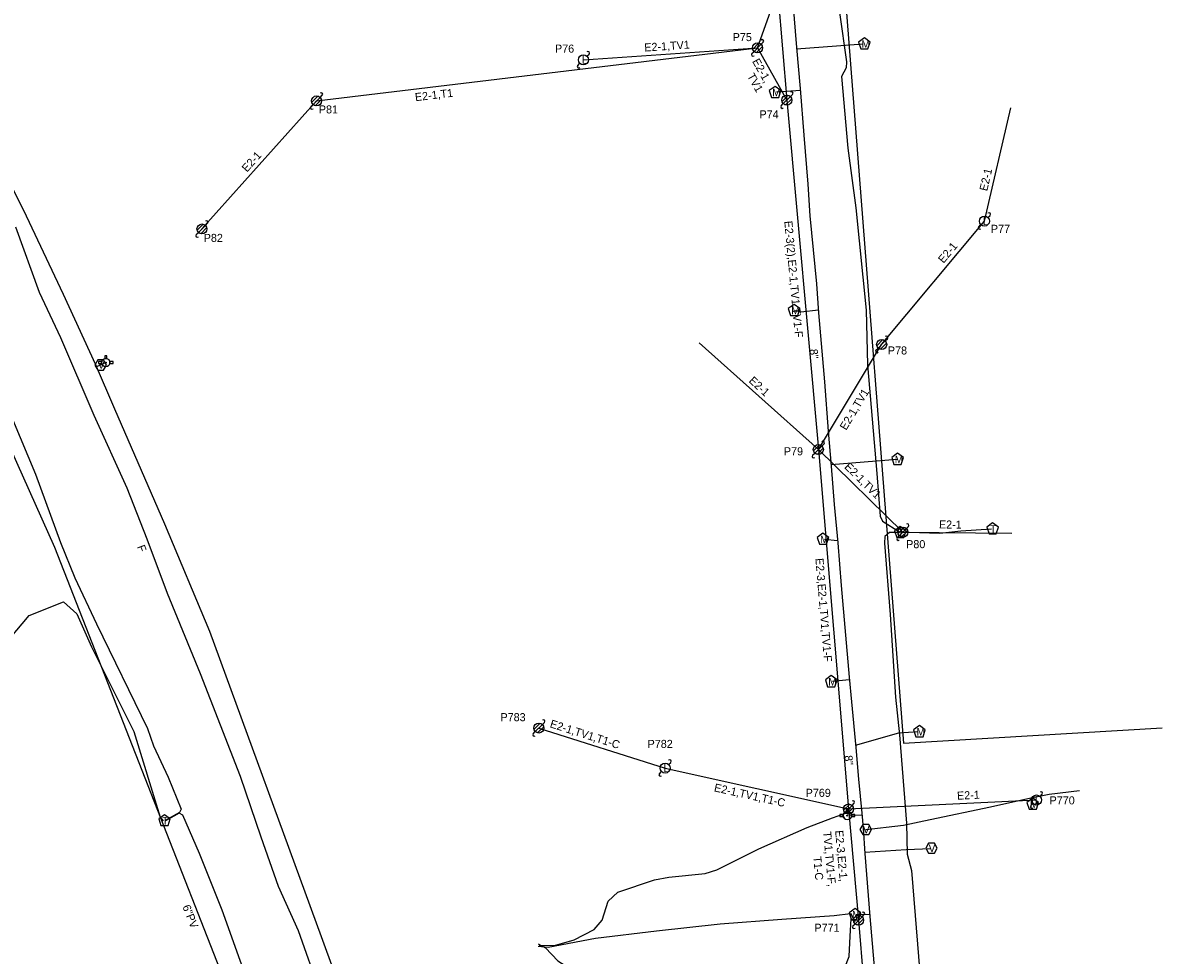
# Model space of a CAD drawing. Extents: x 1741604 to 1825760, y 1164229 to 1194908.
# Drawn here: x 1755902 to 1756469, y 1167980 to 1168443 of the extents above; entities that cross this region are included whole.
import ezdxf

# ---------------------------------------------------------------- set-up
doc = ezdxf.new("R2010")
doc.units = 0
for name, color, linetype in [('RD_EX_SU_Elec', 7, 'Continuous'), ('RD_EX_SU_H2O', 7, 'Continuous'), ('RD_EX_SU_Ovhd', 7, 'Continuous'), ('RD_EX_SU_Pole', 7, 'Continuous'), ('RD_EX_SU_Sewer', 7, 'Continuous'), ('RD_EX_SU_Telecom', 7, 'Continuous'), ('RD_EX_SU_TX_H2O', 7, 'Continuous'), ('RD_EX_SU_TX_Pole', 7, 'Continuous'), ('RD_EX_SU_TX_Sewer', 7, 'Continuous'), ('RD_EX_SU_TX_Telecom', 7, 'Continuous')]:
    doc.layers.add(name, color=color, linetype=linetype)

# ---------------------------------------------------------------- blocks, each defined once
blk = doc.blocks.new('SUE_PP')
at = {"layer": 'RD_EX_SU_Pole'}
for p, q in [((-2.41, -0.65), (0.65, 2.41)), ((-1.77, -1.77), (1.77, 1.77)), ((-0.65, -2.41), (2.41, 0.65)), ((1.77, 1.77), (2.83, 2.83)), ((-2.83, -2.83), (-1.77, -1.77))]:
    blk.add_line(p, q, dxfattribs=at)
blk.add_circle((0, 0), 2.5, dxfattribs=at)
for centre, start, end in [((2.3, 3.36), 315, 135), ((-2.3, -3.36), 135, 315)]:
    blk.add_arc(centre, 0.75, start, end, dxfattribs=at)
blk = doc.blocks.new('SUE_WM')
at = {"layer": 'RD_EX_SU_H2O'}
blk.add_lwpolyline([(0, 3.05), (-2.9, 0.94), (-1.79, -2.47), (1.79, -2.47), (2.9, 0.94)], close=True, dxfattribs=at)
blk.add_text('M', height=3.75, dxfattribs=at).set_placement((-1.43, -1.88))
blk = doc.blocks.new('SUE_TPP')
at = {"layer": 'RD_EX_SU_Telecom'}
blk.add_lwpolyline([(0, 3), (-2.85, 0.93), (-1.76, -2.43), (1.76, -2.43), (2.85, 0.93)], close=True, dxfattribs=at)
blk.add_text('T', height=3.75, dxfattribs=at).set_placement((-1.25, -1.88))
blk = doc.blocks.new('SUE_WFH')
at = {"layer": 'RD_EX_SU_H2O'}
for p, q in [((-2.01, 0.6), (-3.65, 0.6)), ((-3.65, 0.6), (-3.65, -0.45)), ((-0.48, 3.38), (-0.48, 2.04)), ((0.57, 3.38), (-0.48, 3.38)), ((0.57, 2.02), (0.57, 3.38)), ((3.7, 0.6), (2.01, 0.6)), ((3.7, -0.45), (3.7, 0.6)), ((-3.65, -0.45), (-2.05, -0.45)), ((2.05, -0.45), (3.7, -0.45))]:
    blk.add_line(p, q, dxfattribs=at)
for radius in [2.1, 0.263]:
    blk.add_circle((0, 0), radius, dxfattribs=at)
for start, end in [(163.3387, 192.315), (74.2455, 103.2128), (347.685, 16.6613)]:
    blk.add_arc((0, 0), 2.1, start, end, dxfattribs=at)
blk = doc.blocks.new('SUE_WV')
at = {"layer": 'RD_EX_SU_H2O'}
blk.add_lwpolyline([(2.89, 0), (1.44, 2.5), (-1.44, 2.5), (-2.89, 0), (-1.44, -2.5), (1.44, -2.5)], close=True, dxfattribs=at)
blk.add_text('V', height=3.75, dxfattribs=at).set_placement((-1.43, -1.88))

msp = doc.modelspace()

# ---------------------------------------------------------------- linework, layer by layer
at = {"layer": 'RD_EX_SU_Elec'}
msp.add_lwpolyline([(1756158.7, 1167983.99), (1756163.59, 1167983.56), (1756187.17, 1167988.03), (1756217.4, 1167991.66), (1756249.02, 1167995.12), (1756279.77, 1167997.42), (1756305.79, 1167999.38), (1756313.88, 1168000.27), (1756316.19, 1167996.26)], dxfattribs=at)
at = {"layer": 'RD_EX_SU_H2O'}
for p, q in [((1756287.04, 1168430.3), (1756320.14, 1168432.8)), ((1756288.92, 1168409.56), (1756276.99, 1168408.7)), ((1755943.15, 1168273.87), (1755939.17, 1168272.13)), ((1756304.2, 1168223.57), (1756336.98, 1168226.24)), ((1756307.47, 1168185.66), (1756300.96, 1168186.31)), ((1756313.25, 1168116.46), (1756304.98, 1168115.68)), ((1756404.41, 1168055.03), (1756404.06, 1168057.9)), ((1756319.41, 1168049.21), (1756313.16, 1168048.96)), ((1756323.32, 1167999.75), (1756316.73, 1167999.65))]:
    msp.add_line(p, q, dxfattribs=at)
for points in [[(1755726.87, 1168521.3), (1755747.63, 1168505.06), (1755777.82, 1168480.62), (1755829.49, 1168441.52), (1755856.27, 1168421.17), (1755874.43, 1168407.88), (1755891.14, 1168373.18), (1755904.2, 1168347.14)], [(1756285.17, 1168453.36), (1756286.98, 1168430.89), (1756288.84, 1168410.54), (1756290.69, 1168387.38), (1756292.59, 1168362.89), (1756293.61, 1168347.16), (1756296.92, 1168313.47), (1756298.02, 1168299), (1756300.93, 1168264.73), (1756302.72, 1168240.2), (1756304.28, 1168222.7), (1756305.65, 1168203.75), (1756307.59, 1168184.55), (1756309.19, 1168163.34), (1756313.11, 1168117.87), (1756314.27, 1168105.58), (1756316.49, 1168082.9), (1756317.85, 1168067.08)], [(1755904.2, 1168347.14), (1755922.61, 1168308.3), (1755938.52, 1168273.68), (1755948, 1168251.19), (1755972.99, 1168194.09), (1755995.27, 1168140.77), (1756050.84, 1167988.86), (1756081.08, 1167905.61)], [(1756297.93, 1168300.23), (1756289.24, 1168299.38), (1756286.37, 1168299.96)], [(1756316.37, 1168084.09), (1756337.79, 1168090.19), (1756347.49, 1168090.77)], [(1756317.85, 1168067.08), (1756319.54, 1168050.19), (1756320.11, 1168042.67), (1756320.97, 1168030.07), (1756323.39, 1167998.84), (1756327.05, 1167956.56), (1756331.25, 1167904.83), (1756337.4, 1167830.13), (1756339.37, 1167804.89), (1756341.64, 1167782.73), (1756346.05, 1167725.54), (1756348.16, 1167704.76), (1756350.69, 1167674.25), (1756356.07, 1167614.92), (1756363.99, 1167527.76)], [(1756320.16, 1168041.86), (1756340.19, 1168044.22), (1756353.43, 1168047.04), (1756383.46, 1168053.37), (1756403.52, 1168057.78), (1756412.53, 1168059.65), (1756427.58, 1168061.53)], [(1756320.92, 1168030.83), (1756341.5, 1168032.11), (1756353.7, 1168032.64)]]:
    msp.add_lwpolyline(points, dxfattribs=at)
at = {"layer": 'RD_EX_SU_Ovhd'}
for p, q in [((1756267.62, 1168578.94), (1756282.23, 1168404.77)), ((1756267.68, 1168430.74), (1756309.52, 1168548.91)), ((1756048.5, 1168404.33), (1756267.68, 1168430.74)), ((1756181.09, 1168424.8), (1756267.68, 1168430.74)), ((1756267.68, 1168430.74), (1756282.23, 1168404.77)), ((1756282.23, 1168404.77), (1756297.87, 1168230.98)), ((1755991.54, 1168340.68), (1756048.5, 1168404.33)), ((1756380.41, 1168344.61), (1756393.49, 1168400.89)), ((1756329.33, 1168283.25), (1756380.41, 1168344.61)), ((1756238.72, 1168284), (1756297.87, 1168230.98)), ((1756297.87, 1168230.98), (1756329.33, 1168283.25)), ((1756297.87, 1168230.98), (1756339.88, 1168189.94)), ((1756297.87, 1168230.98), (1756312.84, 1168052.28)), ((1756339.88, 1168189.94), (1756394.05, 1168189.45)), ((1756158.95, 1168092.53), (1756221.7, 1168072.64)), ((1756221.7, 1168072.64), (1756312.84, 1168052.28)), ((1756312.84, 1168052.28), (1756406.3, 1168056.76)), ((1756312.84, 1168052.28), (1756317.86, 1167996.94)), ((1756317.86, 1167996.94), (1756327.05, 1167883.97))]:
    msp.add_line(p, q, dxfattribs=at)
at = {"layer": 'RD_EX_SU_Pole'}
for p, q in [((1756182.85, 1168426.57), (1756183.92, 1168427.63)), ((1756178.26, 1168421.98), (1756179.32, 1168423.04)), ((1756046.08, 1168403.69), (1756049.15, 1168406.75)), ((1756046.73, 1168402.57), (1756050.27, 1168406.1)), ((1756047.85, 1168401.92), (1756050.91, 1168404.98)), ((1756050.27, 1168406.1), (1756051.33, 1168407.16)), ((1756045.67, 1168401.51), (1756046.73, 1168402.57)), ((1755989.13, 1168340.03), (1755992.19, 1168343.1)), ((1755989.78, 1168338.91), (1755993.31, 1168342.45)), ((1755993.31, 1168342.45), (1755994.37, 1168343.51)), ((1756377.58, 1168341.79), (1756378.65, 1168342.85)), ((1756382.18, 1168346.38), (1756383.24, 1168347.44)), ((1755988.72, 1168337.85), (1755989.78, 1168338.91)), ((1755990.9, 1168338.27), (1755993.96, 1168341.33)), ((1756337.46, 1168189.29), (1756340.52, 1168192.35)), ((1756338.11, 1168188.17), (1756341.64, 1168191.71)), ((1756339.23, 1168187.53), (1756342.29, 1168190.59)), ((1756341.64, 1168191.71), (1756342.7, 1168192.77)), ((1756337.05, 1168187.11), (1756338.11, 1168188.17)), ((1756218.87, 1168069.81), (1756219.93, 1168070.87)), ((1756223.47, 1168074.41), (1756224.53, 1168075.47)), ((1756408.06, 1168058.53), (1756409.12, 1168059.59)), ((1756403.47, 1168053.93), (1756404.53, 1168054.99))]:
    msp.add_line(p, q, dxfattribs=at)
for centre in [(1756181.09, 1168424.8), (1756048.5, 1168404.33), (1755991.54, 1168340.68), (1756380.41, 1168344.61), (1756339.88, 1168189.94), (1756221.7, 1168072.64), (1756406.3, 1168056.76)]:
    msp.add_circle(centre, 2.5, dxfattribs=at)
for centre, start, end in [((1756183.39, 1168428.16), 315, 135), ((1756178.79, 1168421.45), 135, 315), ((1756050.8, 1168407.69), 315, 135), ((1756046.2, 1168400.98), 135, 315), ((1756382.71, 1168347.97), 315, 135), ((1755993.84, 1168344.04), 315, 135), ((1755989.25, 1168337.32), 135, 315), ((1756378.11, 1168341.26), 135, 315), ((1756342.17, 1168193.3), 315, 135), ((1756337.58, 1168186.58), 135, 315), ((1756224, 1168076), 315, 135), ((1756219.4, 1168069.28), 135, 315), ((1756408.59, 1168060.12), 315, 135), ((1756404, 1168053.4), 135, 315)]:
    msp.add_arc(centre, 0.75, start, end, dxfattribs=at)
at = {"layer": 'RD_EX_SU_Sewer'}
for points in [[(1756311.13, 1168456.78), (1756340.11, 1168085.05), (1756468.76, 1168092.7)], [(1755893.01, 1168238.82), (1755918.27, 1168182.4)], [(1755918.27, 1168182.4), (1756052.9, 1167838.38)]]:
    msp.add_lwpolyline(points, dxfattribs=at)
at = {"layer": 'RD_EX_SU_Telecom'}
for points in [[(1756308.42, 1168448.32), (1756311.91, 1168423.81), (1756311.76, 1168420.79), (1756309.33, 1168416.48), (1756312.58, 1168380.89), (1756316.49, 1168351.19), (1756321.57, 1168300.36), (1756322.32, 1168273.16), (1756326.95, 1168219.13), (1756328.55, 1168197.8), (1756329.78, 1168195.34), (1756338.22, 1168190.16)], [(1755898.9, 1168341.72), (1755910.59, 1168309.21), (1755921.23, 1168286.67), (1755937.77, 1168248.04), (1755954.25, 1168211.92), (1755964.15, 1168186.62), (1755974.26, 1168159.56), (1755990.65, 1168119.67), (1756010.52, 1168068.56), (1756020.83, 1168038.51), (1756029.44, 1168013.84), (1756039.32, 1167991.87), (1756050.05, 1167961.32)], [(1755867.59, 1168310.21), (1755881.89, 1168280.5), (1755897.42, 1168246.03), (1755908.8, 1168218.82), (1755921.3, 1168184.71), (1755928.36, 1168167.28), (1755939.17, 1168144.41), (1755964.51, 1168092.26), (1755967.52, 1168083.62), (1755974.77, 1168068.14), (1755981.19, 1168052.22), (1755980.43, 1168050.52), (1755973.2, 1168046.59)], [(1756338.16, 1168189.78), (1756333.21, 1168189.81), (1756330.86, 1168187.79), (1756330.68, 1168184.52), (1756333.54, 1168148.9), (1756336.25, 1168107.92), (1756338.14, 1168089.1), (1756341.61, 1168045.19), (1756342.02, 1168029.89), (1756344.16, 1168021.72), (1756348.34, 1167970.86), (1756350.41, 1167945.66), (1756353.23, 1167942.43), (1756359.64, 1167942.51)], [(1756339.2, 1168190.05), (1756342.94, 1168189.85), (1756358.25, 1168189.37), (1756368.67, 1168190.63), (1756383.86, 1168191.61)], [(1755841.43, 1168116.92), (1755859.36, 1168120.98), (1755879.61, 1168126.12), (1755888.56, 1168129.53), (1755896.09, 1168137.04), (1755905.65, 1168148.43), (1755922.68, 1168155.3), (1755929.27, 1168149.29), (1755936.61, 1168132.87), (1755957.75, 1168090.78), (1755970.78, 1168048.13), (1755972.19, 1168046.47)], [(1756034.61, 1167874.06), (1756040.08, 1167876.29), (1756045.63, 1167877.54), (1756046.82, 1167879.95), (1756036.25, 1167909.07), (1756027.29, 1167930.71), (1756020.62, 1167949.2), (1756010.49, 1167977), (1756001.55, 1168001.89), (1755990.3, 1168030.08), (1755982.09, 1168049.19), (1755980.19, 1168050.16), (1755973.48, 1168046.32)], [(1756159.04, 1167984.63), (1756166.68, 1167984.37), (1756176.55, 1167987.23), (1756186.47, 1167992.4), (1756190.44, 1167996.92), (1756193.4, 1168006.42), (1756198.16, 1168010.87), (1756216.42, 1168016.99), (1756223.51, 1168018.39), (1756241.64, 1168020.25), (1756247.48, 1168021.99), (1756268.27, 1168032.44), (1756292.3, 1168043.12), (1756304.83, 1168047.91), (1756313.37, 1168050.78), (1756313.03, 1168052.57)], [(1756158.59, 1167985.22), (1756162.2, 1167983.17), (1756168.33, 1167976.76), (1756180.21, 1167969.34), (1756190.12, 1167968.53), (1756236.31, 1167970.8), (1756263.75, 1167971.46), (1756299.2, 1167970.68), (1756307.27, 1167971.19), (1756311.09, 1167973.51), (1756313.18, 1167978.88), (1756313.61, 1167989.06), (1756314.16, 1167997.74), (1756316.41, 1167997.29)]]:
    msp.add_lwpolyline(points, dxfattribs=at)

# ---------------------------------------------------------------- block references
at = {"layer": 'RD_EX_SU_H2O'}
for name, p in [('SUE_WM', (1756320.75, 1168432.64)), ('SUE_WM', (1756276.37, 1168408.55)), ('SUE_WM', (1756285.82, 1168300.15)), ('SUE_WV', (1755941.23, 1168273.04)), ('SUE_WFH', (1755943.71, 1168274.21)), ('SUE_WM', (1756337.24, 1168226.1)), ('SUE_WM', (1756300.18, 1168186.37)), ('SUE_WM', (1756304.26, 1168115.55)), ('SUE_WM', (1756348.09, 1168090.67)), ('SUE_WM', (1756404.46, 1168054.62)), ('SUE_WFH', (1756312.24, 1168049.01)), ('SUE_WV', (1756321.45, 1168042.03)), ('SUE_WV', (1756354.1, 1168032.8)), ('SUE_WM', (1756316.09, 1167999.71))]:
    msp.add_blockref(name, p, dxfattribs=at)
at = {"layer": 'RD_EX_SU_Pole'}
for p in [(1756267.68, 1168430.74), (1756282.23, 1168404.77), (1756329.33, 1168283.25), (1756297.87, 1168230.98), (1756158.95, 1168092.53), (1756312.84, 1168052.28), (1756317.86, 1167996.94)]:
    msp.add_blockref('SUE_PP', p, dxfattribs=at)
at = {"layer": 'RD_EX_SU_Telecom'}
for p in [(1756338.61, 1168189.72), (1756384.5, 1168191.53), (1755972.92, 1168046.44)]:
    msp.add_blockref('SUE_TPP', p, dxfattribs=at)

# ---------------------------------------------------------------- texts
at = {"layer": 'RD_EX_SU_Ovhd'}
for s, rotation, p in [('E2-1,TV1', 3.9019, (1756211.52, 1168428.88)), ('E2-1,', 299.2194, (1756264.87, 1168424.05)), ('TV1', 299.2194, (1756262.34, 1168416.76)), ('E2-1,T1', 6.8583, (1756097.64, 1168404.2)), ('E2-1', 48.1784, (1756013.89, 1168368.65)), ('E2-1', 76.9188, (1756381.76, 1168359.27)), ('E2-3(2),E2-1,TV1,TV1-F', 275.2484, (1756280.94, 1168344.53)), ('E2-1', 50.2209, (1756360.08, 1168323.31)), ('E2-1', 317.5737, (1756263, 1168264.78)), ('E2-1,TV1', 59.1195, (1756311.68, 1168240.3)), ('E2-1,TV1', 315.4477, (1756310.53, 1168222.04)), ('E2-1', 359.4792, (1756357.8, 1168191.78)), ('E2-3,E2-1,TV1,TV1-F', 274.7869, (1756296.39, 1168176.83)), ('E2-1,TV1,T1-C', 342.4139, (1756164.15, 1168092.98)), ('E2-1,TV1,T1-C', 347.406, (1756245.77, 1168061.11)), ('E2-1', 2.7473, (1756366.89, 1168056.87)), ('TV1,TV1-F,', 275.1834, (1756300.22, 1168040.97)), ('E2-3,E2-1,', 275.1834, (1756306.2, 1168041.51)), ('T1-C', 275.1834, (1756295.32, 1168028.58))]:
    msp.add_text(s, height=4, rotation=rotation, dxfattribs=at).set_placement(p)
at = {"layer": 'RD_EX_SU_Pole'}
for p in [(1756180.22, 1168422.8), (1756379.55, 1168342.61), (1756220.84, 1168070.64), (1756405.43, 1168054.76)]:
    msp.add_text('L', height=4, dxfattribs=at).set_placement(p)
at = {"layer": 'RD_EX_SU_TX_H2O'}
for rotation, p in [(274.8506, (1756293.54, 1168280.84)), (274.9264, (1756310.82, 1168078.81))]:
    msp.add_text('8"', height=4, rotation=rotation, dxfattribs=at).set_placement(p)
at = {"layer": 'RD_EX_SU_TX_Pole'}
for s, p in [('P75', (1756255.29, 1168434.09)), ('P76', (1756167, 1168428.36)), ('P81', (1756049.63, 1168398.13)), ('P74', (1756268.6, 1168395.68)), ('P77', (1756383.64, 1168338.75)), ('P82', (1755992.41, 1168334.24)), ('P78', (1756332.44, 1168278.27)), ('P79', (1756280.74, 1168228.14)), ('P80', (1756341.51, 1168181.96)), ('P783', (1756139.9, 1168095.93)), ('P782', (1756213.01, 1168082.64)), ('P769', (1756291.57, 1168058.31)), ('P770', (1756412.79, 1168054.56)), ('P771', (1756295.94, 1167991.23))]:
    msp.add_text(s, height=4, dxfattribs=at).set_placement(p)
at = {"layer": 'RD_EX_SU_TX_Sewer'}
msp.add_text('6"PV', height=4, rotation=291.3731, dxfattribs=at).set_placement((1755981.75, 1168003.74))
at = {"layer": 'RD_EX_SU_TX_Telecom'}
msp.add_text('F', height=4, rotation=290.4755, dxfattribs=at).set_placement((1755959.22, 1168182.69))

doc.saveas('drawing.dxf')
